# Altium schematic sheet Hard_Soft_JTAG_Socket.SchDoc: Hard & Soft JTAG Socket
size A4; DocumentNumber: 4; SheetNumber: 4; SheetTotal: 12
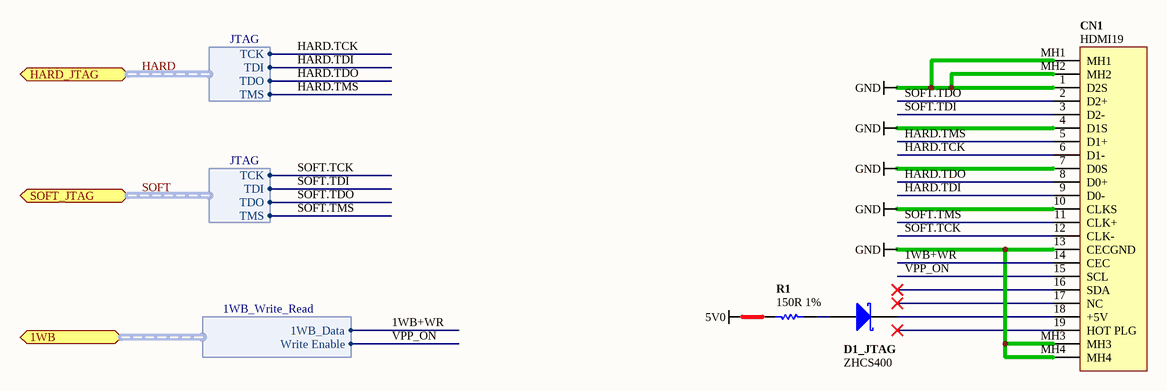
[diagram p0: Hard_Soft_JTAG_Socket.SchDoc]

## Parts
CN1  HDMI19  [G3168-0500XXXX-00]
D1_JTAG  ZHCS400  [SOD323]
R1  150R 1%  [RESC1005-STAR]

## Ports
1WB (harness 1WB_Write_Read), HARD_JTAG (harness JTAG), SOFT_JTAG (harness JTAG)

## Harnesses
1WB_Write_Read: 1WB_Data, Write Enable
JTAG: TCK, TDI, TDO, TMS

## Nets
5V0: R1.1
GND: CN1.1(D2S) CN1.4(D1S) CN1.7(D0S) CN1.10(CLKS) CN1.13(CECGND) CN1.MH1 CN1.MH2 CN1.MH3 CN1.MH4
1WB+WR: CN1.14(CEC) ; port 1WB.1WB_Data
HARD.TCK: CN1.6(D1-) ; port HARD_JTAG.TCK
HARD.TDI: CN1.9(D0-) ; port HARD_JTAG.TDI
HARD.TDO: CN1.8(D0+) ; port HARD_JTAG.TDO
HARD.TMS: CN1.5(D1+) ; port HARD_JTAG.TMS
SOFT.TCK: CN1.12(CLK-) ; port SOFT_JTAG.TCK
SOFT.TDI: CN1.3(D2-) ; port SOFT_JTAG.TDI
SOFT.TDO: CN1.2(D2+) ; port SOFT_JTAG.TDO
SOFT.TMS: CN1.11(CLK+) ; port SOFT_JTAG.TMS
VPP_ON: CN1.15(SCL) ; port 1WB.Write Enable
NetCN1_18: CN1.18(+5V) D1_JTAG.2(K)
NetD1_JTAG_1: D1_JTAG.1(A) R1.2

Not connected (* = marked no-connect by the designer): CN1 16(SDA)* 17(NC)* 19(HOT_PLG)*

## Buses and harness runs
harness HARD = port HARD_JTAG
harness SOFT = port SOFT_JTAG

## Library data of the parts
CN1 = D-300-0058: HDMI Socket; 19 Pin; Connector type: Right Angle; Max Current: mA
D1_JTAG = D-151-0004: Schottky Diode, 400mA; Rated Voltage: mV
R1 = D-100-0005: Resistor, 150R 1% 0402 (1005); Power Rating: 63 mW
